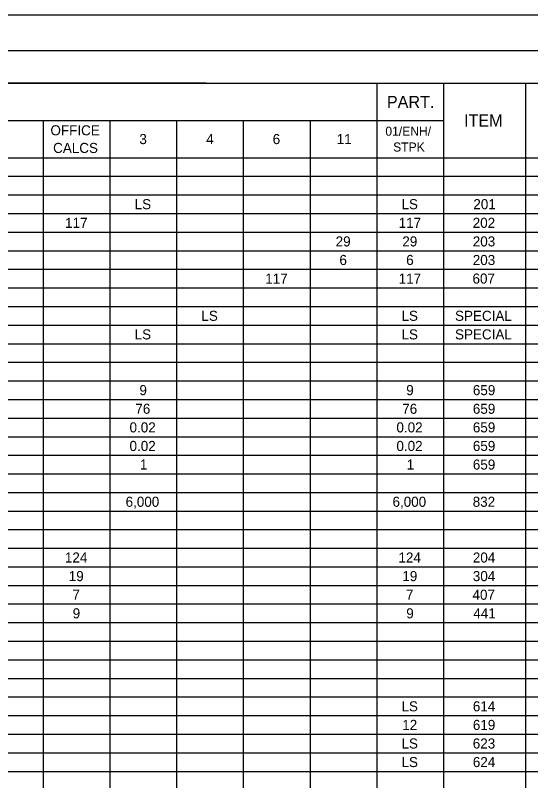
# Model space of a CAD drawing. Extents: x 0 to 34, y 0 to 22.
# Drawn here: x 9.38 to 16.73, y 11.09 to 22 of the extents above; entities that cross this region are included whole.
import ezdxf

# ---------------------------------------------------------------- set-up
doc = ezdxf.new("R2010")
doc.units = 0
for name, color, linetype in [('Default', 7, 'Continuous'), ('SH_Border', 7, 'Continuous'), ('SH_Cut_Line', 7, 'Continuous')]:
    doc.layers.add(name, color=color, linetype=linetype)

msp = doc.modelspace()

# ---------------------------------------------------------------- linework, layer by layer
at = {"layer": 'Default'}
for p, q in [((2.161, 21.03), (31.052, 21.03)), ((14.532, 21.03), (14.532, 6.444)), ((15.483, 21.03), (15.483, 6.444)), ((16.653, 21.03), (16.653, 6.444)), ((2.161, 20.5), (15.483, 20.5)), ((9.774, 20.5), (9.774, 6.444)), ((10.725, 20.5), (10.725, 6.444)), ((11.677, 20.5), (11.677, 6.444)), ((12.628, 20.5), (12.628, 6.444)), ((13.58, 20.5), (13.58, 6.444)), ((2.161, 19.969), (31.052, 19.969)), ((2.161, 19.704), (31.052, 19.704)), ((2.161, 19.439), (31.052, 19.439)), ((2.161, 19.174), (31.052, 19.174)), ((2.161, 18.909), (31.052, 18.909)), ((2.161, 18.643), (31.052, 18.643)), ((2.161, 18.378), (31.052, 18.378)), ((2.161, 18.113), (31.052, 18.113)), ((2.161, 17.848), (31.052, 17.848)), ((2.161, 17.583), (31.052, 17.583)), ((2.161, 17.317), (31.052, 17.317)), ((2.161, 17.052), (31.052, 17.052)), ((2.161, 16.787), (31.052, 16.787)), ((2.161, 16.522), (31.052, 16.522)), ((2.161, 16.257), (31.052, 16.257)), ((2.161, 15.991), (31.052, 15.991)), ((2.161, 15.726), (31.052, 15.726)), ((2.161, 15.461), (31.052, 15.461)), ((2.161, 15.196), (31.052, 15.196)), ((2.161, 14.931), (31.052, 14.931)), ((2.161, 14.665), (31.052, 14.665)), ((2.161, 14.4), (31.052, 14.4)), ((2.161, 14.135), (31.052, 14.135)), ((2.161, 13.87), (31.052, 13.87)), ((2.161, 13.605), (31.052, 13.605)), ((2.161, 13.339), (31.052, 13.339)), ((2.161, 13.074), (31.052, 13.074)), ((2.161, 12.809), (31.052, 12.809)), ((2.161, 12.544), (31.052, 12.544)), ((2.161, 12.279), (31.052, 12.279)), ((2.161, 12.013), (31.052, 12.013)), ((2.161, 11.748), (31.052, 11.748)), ((2.161, 11.483), (31.052, 11.483)), ((2.161, 11.218), (31.052, 11.218))]:
    msp.add_line(p, q, dxfattribs=at)
msp.add_lwpolyline([(2.161, 21.03), (12.098, 21.03), (12.098, 21.03), (2.161, 21.03)], close=True, dxfattribs=at)
msp.add_lwpolyline([(2.161, 21.03), (12.098, 21.03), (12.098, 21.03), (2.161, 21.03)], close=True, dxfattribs=at)
msp.add_lwpolyline([(2.161, 21.03), (12.098, 21.03), (12.098, 21.03), (2.161, 21.03)], close=True, dxfattribs=at)
msp.add_lwpolyline([(2.161, 21.03), (12.098, 21.03), (12.098, 21.03), (2.161, 21.03)], close=True, dxfattribs=at)
msp.add_lwpolyline([(2.161, 21.03), (12.098, 21.03), (12.098, 21.03), (2.161, 21.03)], close=True, dxfattribs=at)
msp.add_lwpolyline([(2.161, 21.03), (12.098, 21.03), (12.098, 21.03), (2.161, 21.03)], close=True, dxfattribs=at)
msp.add_lwpolyline([(2.161, 21.03), (12.098, 21.03), (12.098, 21.03), (2.161, 21.03)], close=True, dxfattribs=at)
msp.add_lwpolyline([(2.161, 21.03), (12.098, 21.03), (12.098, 21.03), (2.161, 21.03)], close=True, dxfattribs=at)
msp.add_lwpolyline([(2.161, 21.03), (12.098, 21.03), (12.098, 21.03), (2.161, 21.03)], close=True, dxfattribs=at)
msp.add_lwpolyline([(2.161, 21.03), (12.098, 21.03), (12.098, 21.03), (2.161, 21.03)], close=True, dxfattribs=at)
msp.add_lwpolyline([(2.161, 21.03), (12.098, 21.03), (12.098, 21.03), (2.161, 21.03)], close=True, dxfattribs=at)
msp.add_lwpolyline([(2.161, 21.03), (12.098, 21.03), (12.098, 21.03), (2.161, 21.03)], close=True, dxfattribs=at)
msp.add_lwpolyline([(2.161, 21.03), (12.098, 21.03), (12.098, 21.03), (2.161, 21.03)], close=True, dxfattribs=at)
msp.add_lwpolyline([(2.161, 21.03), (12.098, 21.03), (12.098, 21.03), (2.161, 21.03)], close=True, dxfattribs=at)
msp.add_lwpolyline([(2.161, 21.03), (12.098, 21.03), (12.098, 21.03), (2.161, 21.03)], close=True, dxfattribs=at)
msp.add_lwpolyline([(2.161, 21.03), (12.098, 21.03), (12.098, 21.03), (2.161, 21.03)], close=True, dxfattribs=at)
msp.add_lwpolyline([(2.161, 21.03), (12.098, 21.03), (12.098, 21.03), (2.161, 21.03)], close=True, dxfattribs=at)
msp.add_lwpolyline([(2.161, 21.03), (12.098, 21.03), (12.098, 21.03), (2.161, 21.03)], close=True, dxfattribs=at)
msp.add_lwpolyline([(2.161, 21.03), (12.098, 21.03), (12.098, 21.03), (2.161, 21.03)], close=True, dxfattribs=at)
msp.add_lwpolyline([(2.161, 21.03), (12.098, 21.03), (12.098, 21.03), (2.161, 21.03)], close=True, dxfattribs=at)
at = {"layer": 'SH_Border'}
msp.add_lwpolyline([(1.5, 21.5), (33.5, 21.5), (33.5, 0.5), (1.5, 0.5)], close=True, dxfattribs=at)
at = {"layer": 'SH_Cut_Line'}
msp.add_lwpolyline([(0, 0), (34, 0), (34, 22), (0, 22)], close=True, dxfattribs=at)

# ---------------------------------------------------------------- texts
at = {"layer": 'Default'}
for s, height, p in [('PART.', 0.1722, (14.676, 20.679)), ('ITEM', 0.1722, (15.776, 20.414)), ('OFFICE ', 0.1435, (9.877, 20.288)), ('01/ENH/', 0.1292, (14.654, 20.283)), ('3', 0.144, (11.145, 20.163)), ('4', 0.144, (12.098, 20.163)), ('6', 0.144, (13.047, 20.163)), ('11', 0.1435, (13.96, 20.163)), ('CALCS', 0.1435, (9.915, 20.037)), ('STPK', 0.1292, (14.765, 20.057)), ('LS', 0.1435, (11.078, 19.235)), ('LS', 0.1435, (14.884, 19.235)), ('201', 0.1435, (15.909, 19.235)), ('117', 0.1435, (10.086, 18.969)), ('117', 0.1435, (14.844, 18.969)), ('202', 0.1435, (15.9, 18.969)), ('29', 0.1435, (13.945, 18.704)), ('29', 0.1435, (14.896, 18.704)), ('203', 0.1435, (15.901, 18.704)), ('6', 0.144, (13.999, 18.439)), ('6', 0.144, (14.951, 18.439)), ('203', 0.1435, (15.901, 18.439)), ('117', 0.1435, (12.941, 18.174)), ('117', 0.1435, (14.844, 18.174)), ('607', 0.1435, (15.897, 18.174)), ('LS', 0.1435, (12.03, 17.643)), ('LS', 0.1435, (14.884, 17.643)), ('SPECIAL', 0.1435, (15.648, 17.643)), ('LS', 0.1435, (11.078, 17.378)), ('LS', 0.1435, (14.884, 17.378)), ('SPECIAL', 0.1435, (15.648, 17.378)), ('9', 0.144, (11.146, 16.583)), ('9', 0.144, (14.952, 16.583)), ('659', 0.1435, (15.902, 16.583)), ('76', 0.1435, (11.088, 16.317)), ('76', 0.1435, (14.895, 16.317)), ('659', 0.1435, (15.902, 16.317)), ('0.02', 0.1435, (11.005, 16.052)), ('0.02', 0.1435, (14.812, 16.052)), ('659', 0.1435, (15.902, 16.052)), ('0.02', 0.1435, (11.005, 15.787)), ('0.02', 0.1435, (14.812, 15.787)), ('659', 0.1435, (15.902, 15.787)), ('1', 0.144, (11.153, 15.522)), ('1', 0.144, (14.959, 15.522)), ('659', 0.1435, (15.902, 15.522)), ('6,000', 0.1435, (10.949, 14.991)), ('6,000', 0.1435, (14.756, 14.991)), ('832', 0.1435, (15.9, 14.991)), ('124', 0.1435, (10.083, 14.196)), ('124', 0.1435, (14.841, 14.196)), ('204', 0.1435, (15.902, 14.196)), ('19', 0.1435, (10.138, 13.931)), ('19', 0.1435, (14.896, 13.931)), ('304', 0.1435, (15.902, 13.931)), ('7', 0.144, (10.19, 13.665)), ('7', 0.144, (14.948, 13.665)), ('407', 0.1435, (15.897, 13.665)), ('9', 0.144, (10.194, 13.4)), ('9', 0.144, (14.952, 13.4)), ('441', 0.1435, (15.909, 13.4)), ('LS', 0.1435, (14.884, 12.074)), ('614', 0.1435, (15.902, 12.074)), ('12', 0.1435, (14.895, 11.809)), ('619', 0.1435, (15.902, 11.809)), ('LS', 0.1435, (14.884, 11.544)), ('623', 0.1435, (15.901, 11.544)), ('LS', 0.1435, (14.884, 11.279)), ('624', 0.1435, (15.902, 11.279))]:
    msp.add_text(s, height=height, dxfattribs=at).set_placement(p)

doc.saveas('drawing.dxf')
